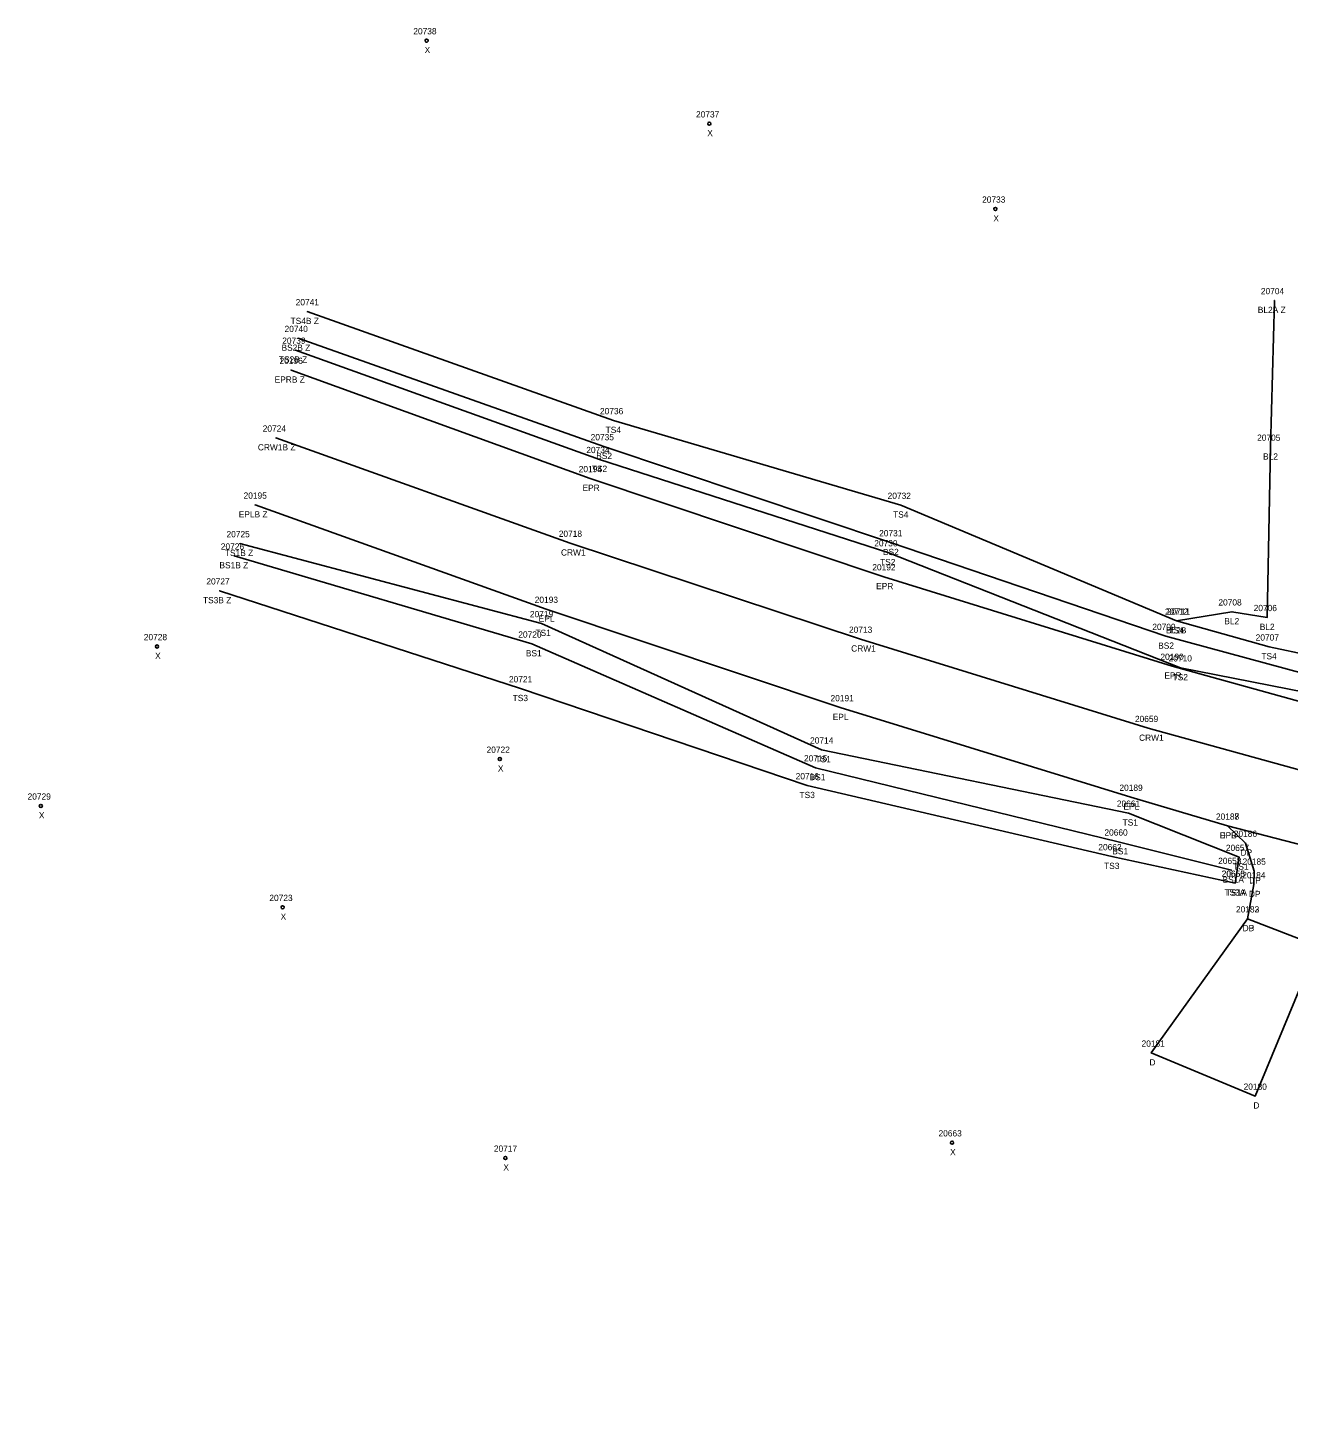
# Model space of a CAD drawing. Extents: x 1813127 to 1814107, y 1178171 to 1179078.
# Drawn here: x 1813127 to 1813328.5, y 1178708 to 1178931.8 of the extents above; entities that cross this region are included whole.
import ezdxf

# ---------------------------------------------------------------- set-up
doc = ezdxf.new("R2010")
doc.units = 0
for name, color, linetype in [('RD_DTM_BkLn1', 7, 'Continuous'), ('RD_DTM_BkLn2', 7, 'Continuous'), ('RD_EX_Driveway', 7, 'Continuous'), ('RD_EX_Driveway_txCode', 7, 'Continuous'), ('RD_EX_Road', 7, 'Continuous'), ('RD_EX_Road_txCode', 7, 'Continuous'), ('RD_SMD_Locator', 7, 'Continuous'), ('RD_SMD_Misc', 7, 'Continuous')]:
    doc.layers.add(name, color=color, linetype=linetype)

msp = doc.modelspace()

# ---------------------------------------------------------------- linework, layer by layer
at = {"layer": 'RD_DTM_BkLn1'}
for points in [[(1813326.2, 1178888.27), (1813325.6, 1178864.83), (1813325.07, 1178837.59), (1813319.4, 1178838.49), (1813310.54, 1178837.02)], [(1813740.76, 1178717.86), (1813693.97, 1178742.65), (1813652.18, 1178753.85), (1813643.74, 1178755.64), (1813595, 1178763.51), (1813546.44, 1178770.61), (1813497.6, 1178777.62), (1813448.59, 1178785.89), (1813401.09, 1178795.04), (1813353.48, 1178806.76), (1813306.05, 1178819.85), (1813260.03, 1178834.12), (1813213.64, 1178849.47), (1813166.61, 1178866.29)]]:
    msp.add_lwpolyline(points, dxfattribs=at)
at = {"layer": 'RD_DTM_BkLn2'}
for points in [[(1813399.11, 1178862.51), (1813400.66, 1178834.59), (1813396.83, 1178814.37), (1813357.41, 1178822.74), (1813331.9, 1178831.52), (1813325.37, 1178832.88), (1813310.54, 1178837.02), (1813266.49, 1178855.54), (1813220.54, 1178869.08), (1813171.6, 1178886.5)], [(1813400.27, 1178862.81), (1813401.78, 1178834.6), (1813398.4, 1178812.49), (1813398.37, 1178811.29), (1813357.2, 1178821.49), (1813308.85, 1178834.57), (1813264.85, 1178849.55), (1813219.03, 1178864.91), (1813170.13, 1178882.22)], [(1813401.59, 1178862.81), (1813403.02, 1178834.61), (1813400.13, 1178813.23), (1813399.37, 1178809.66), (1813357.07, 1178820.51), (1813311.17, 1178829.54), (1813264.4, 1178847.94), (1813218.33, 1178862.86), (1813169.73, 1178880.34)], [(1813319.93, 1178795.1), (1813320.59, 1178799.23), (1813302.9, 1178806.3), (1813253.81, 1178816.41), (1813209.04, 1178836.62), (1813160.82, 1178849.4)], [(1813319.35, 1178797.15), (1813301.23, 1178801.69), (1813252.84, 1178813.55), (1813207.5, 1178833.35), (1813159.94, 1178847.43)], [(1813319.93, 1178795.1), (1813300.22, 1178799.35), (1813251.54, 1178810.69), (1813205.69, 1178826.2), (1813157.6, 1178841.85)]]:
    msp.add_lwpolyline(points, dxfattribs=at)
at = {"layer": 'RD_EX_Driveway'}
for points in [[(1813343.23, 1178797.92), (1813338.76, 1178793.46), (1813333.1, 1178785.04), (1813321.9, 1178789.4), (1813322.9, 1178794.86), (1813322.95, 1178797.03), (1813321.57, 1178801.49), (1813318.7, 1178804.23)], [(1813333.1, 1178785.04), (1813323.15, 1178761.04), (1813306.52, 1178767.93), (1813321.9, 1178789.4)]]:
    msp.add_lwpolyline(points, dxfattribs=at)
at = {"layer": 'RD_EX_Road'}
for points in [[(1813499.47, 1178787.87), (1813450.56, 1178796.06), (1813414.35, 1178802.92), (1813398.64, 1178806.42), (1813355.44, 1178817.13), (1813309.85, 1178829.79), (1813263.76, 1178844.1), (1813216.84, 1178859.81), (1813169.03, 1178877.13)], [(1813732.94, 1178707.95), (1813689.88, 1178731.75), (1813641.71, 1178744.36), (1813593.37, 1178752.09), (1813544.49, 1178758.77), (1813495.45, 1178766.29), (1813446.8, 1178774.66), (1813426.54, 1178777.95), (1813403.21, 1178782.55), (1813398.65, 1178783.84), (1813350.68, 1178796.09), (1813343.23, 1178797.92), (1813318.7, 1178804.23), (1813303.26, 1178808.85), (1813256.8, 1178823.17), (1813209.81, 1178838.91), (1813163.27, 1178855.57)]]:
    msp.add_lwpolyline(points, dxfattribs=at)
at = {"layer": 'RD_SMD_Locator'}
for centre, radius in [((1813190.68, 1178929.83), 0.25), ((1813235.87, 1178916.54), 0.25), ((1813281.6, 1178902.91), 0.25), ((1813326.2, 1178888.27), 0.001), ((1813171.6, 1178886.5), 0.001), ((1813170.13, 1178882.22), 0.001), ((1813169.73, 1178880.34), 0.001), ((1813169.03, 1178877.13), 0.001), ((1813220.54, 1178869.08), 0.001), ((1813166.61, 1178866.29), 0.001), ((1813219.03, 1178864.91), 0.001), ((1813325.6, 1178864.83), 0.001), ((1813218.33, 1178862.86), 0.001), ((1813216.84, 1178859.81), 0.001), ((1813163.27, 1178855.57), 0.001), ((1813266.49, 1178855.54), 0.001), ((1813160.82, 1178849.4), 0.001), ((1813213.64, 1178849.47), 0.001), ((1813264.4, 1178847.94), 0.001), ((1813264.85, 1178849.55), 0.001), ((1813159.94, 1178847.43), 0.001), ((1813263.76, 1178844.1), 0.001), ((1813157.6, 1178841.85), 0.001), ((1813209.81, 1178838.91), 0.001), ((1813310.54, 1178837.02), 0.001), ((1813310.54, 1178837.02), 0.001), ((1813319.4, 1178838.49), 0.001), ((1813325.07, 1178837.59), 0.001), ((1813209.04, 1178836.62), 0.001), ((1813308.85, 1178834.57), 0.001), ((1813147.6, 1178832.94), 0.25), ((1813207.5, 1178833.35), 0.001), ((1813260.03, 1178834.12), 0.001), ((1813325.37, 1178832.88), 0.001), ((1813309.85, 1178829.79), 0.001), ((1813311.17, 1178829.54), 0.001), ((1813205.69, 1178826.2), 0.001), ((1813256.8, 1178823.17), 0.001), ((1813306.05, 1178819.85), 0.001), ((1813202.39, 1178814.93), 0.25), ((1813253.81, 1178816.41), 0.001), ((1813252.84, 1178813.55), 0.001), ((1813251.54, 1178810.69), 0.001), ((1813129.02, 1178807.44), 0.25), ((1813303.26, 1178808.85), 0.001), ((1813302.9, 1178806.3), 0.001), ((1813318.7, 1178804.23), 0.001), ((1813318.7, 1178804.23), 0.001), ((1813301.23, 1178801.69), 0.001), ((1813321.57, 1178801.49), 0.001), ((1813300.22, 1178799.35), 0.001), ((1813320.59, 1178799.23), 0.001), ((1813319.35, 1178797.15), 0.001), ((1813322.95, 1178797.03), 0.001), ((1813319.93, 1178795.1), 0.001), ((1813319.93, 1178795.1), 0.001), ((1813322.9, 1178794.86), 0.001), ((1813167.67, 1178791.23), 0.25), ((1813321.9, 1178789.4), 0.001), ((1813321.9, 1178789.4), 0.001), ((1813306.52, 1178767.93), 0.001), ((1813323.15, 1178761.04), 0.001), ((1813274.67, 1178753.58), 0.25), ((1813203.27, 1178751.13), 0.25)]:
    msp.add_circle(centre, radius, dxfattribs=at)

# ---------------------------------------------------------------- texts
at = {"layer": 'RD_EX_Driveway_txCode'}
for s, p in [('20187', (1813316.86, 1178805.23)), ('DPB', (1813317.44, 1178802.23)), ('20186', (1813319.71, 1178802.49)), ('DP', (1813320.79, 1178799.49)), ('20185', (1813321.11, 1178798.03)), ('20184', (1813321.06, 1178795.86)), ('DP', (1813322.17, 1178795.03)), ('DP', (1813322.12, 1178792.86)), ('20182', (1813320.06, 1178790.4)), ('20183', (1813320.06, 1178790.4)), ('DB', (1813321.12, 1178787.4)), ('DP', (1813321.12, 1178787.4)), ('20181', (1813304.97, 1178768.93)), ('D', (1813306.22, 1178765.93)), ('20180', (1813321.28, 1178762.04)), ('D', (1813322.84, 1178759.04))]:
    msp.add_text(s, height=1, dxfattribs=at).set_placement(p)
at = {"layer": 'RD_EX_Road_txCode'}
for s, p in [('20196', (1813167.17, 1178878.13)), ('EPRB Z', (1813166.39, 1178875.13)), ('20194', (1813215, 1178860.81)), ('20195', (1813161.43, 1178856.57)), ('EPR', (1813215.61, 1178857.81)), ('EPLB Z', (1813160.65, 1178853.57)), ('20192', (1813261.93, 1178845.1)), ('EPR', (1813262.54, 1178842.1)), ('20193', (1813207.97, 1178839.91)), ('EPL', (1813208.6, 1178836.91)), ('20190', (1813307.98, 1178830.79)), ('EPR', (1813308.62, 1178827.79)), ('20191', (1813255.25, 1178824.17)), ('EPL', (1813255.6, 1178821.17)), ('20189', (1813301.43, 1178809.85)), ('EPL', (1813302.06, 1178806.85)), ('20188', (1813316.86, 1178805.23)), ('EPL', (1813317.49, 1178802.23))]:
    msp.add_text(s, height=1, dxfattribs=at).set_placement(p)
at = {"layer": 'RD_SMD_Misc'}
for s, p in [('20738', (1813188.56, 1178930.83)), ('X', (1813190.37, 1178927.83)), ('20737', (1813233.75, 1178917.54)), ('X', (1813235.55, 1178914.54)), ('20733', (1813279.48, 1178903.91)), ('X', (1813281.28, 1178900.91)), ('20741', (1813169.76, 1178887.5)), ('20704', (1813324.04, 1178889.27)), ('BL2A Z', (1813323.55, 1178886.27)), ('20740', (1813167.98, 1178883.22)), ('TS4B Z', (1813168.94, 1178884.5)), ('20739', (1813167.61, 1178881.34)), ('TS2B Z', (1813167.07, 1178878.34)), ('BS2B Z', (1813167.49, 1178880.22)), ('20736', (1813218.4, 1178870.08)), ('20724', (1813164.49, 1178867.29)), ('TS4', (1813219.3, 1178867.08)), ('20735', (1813216.91, 1178865.91)), ('20705', (1813323.44, 1178865.83)), ('CRW1B Z', (1813163.71, 1178864.29)), ('20734', (1813216.21, 1178863.86)), ('BS2', (1813217.8, 1178862.91)), ('BL2', (1813324.39, 1178862.83)), ('TS2', (1813217.09, 1178860.86)), ('20732', (1813264.38, 1178856.54)), ('TS4', (1813265.25, 1178853.54)), ('20725', (1813158.7, 1178850.4)), ('20718', (1813211.81, 1178850.47)), ('20731', (1813263.02, 1178850.55)), ('20726', (1813157.79, 1178848.43)), ('TS1B Z', (1813158.44, 1178847.4)), ('CRW1', (1813212.16, 1178847.47)), ('20730', (1813262.24, 1178848.94)), ('BS2', (1813263.63, 1178847.55)), ('BS1B Z', (1813157.57, 1178845.43)), ('TS2', (1813263.16, 1178845.94)), ('20727', (1813155.48, 1178842.85)), ('TS3B Z', (1813154.94, 1178839.85)), ('20712', (1813308.71, 1178838.02)), ('20711', (1813308.99, 1178838.02)), ('20708', (1813317.25, 1178839.49)), ('20706', (1813322.89, 1178838.59)), ('20719', (1813207.2, 1178837.62)), ('BL2', (1813318.2, 1178836.49)), ('20728', (1813145.48, 1178833.94)), ('20720', (1813205.34, 1178834.35)), ('TS1', (1813208.08, 1178834.62)), ('20713', (1813258.2, 1178835.12)), ('20709', (1813306.69, 1178835.57)), ('BL2B', (1813308.86, 1178835.02)), ('TS4', (1813309.3, 1178835.02)), ('20707', (1813323.21, 1178833.88)), ('BL2', (1813323.86, 1178835.59)), ('BS1', (1813206.55, 1178831.35)), ('CRW1', (1813258.55, 1178832.12)), ('BS2', (1813307.62, 1178832.57)), ('X', (1813147.29, 1178830.94)), ('20710', (1813309.3, 1178830.54)), ('TS4', (1813324.12, 1178830.88)), ('20721', (1813203.85, 1178827.2)), ('TS2', (1813309.93, 1178827.54)), ('TS3', (1813204.44, 1178824.2)), ('20659', (1813303.91, 1178820.85)), ('CRW1', (1813304.57, 1178817.85)), ('20722', (1813200.27, 1178815.93)), ('20714', (1813251.98, 1178817.41)), ('20715', (1813251.01, 1178814.55)), ('TS1', (1813252.85, 1178814.41)), ('X', (1813202.08, 1178812.93)), ('20716', (1813249.68, 1178811.69)), ('BS1', (1813251.9, 1178811.55)), ('20729', (1813126.9, 1178808.44)), ('TS3', (1813250.29, 1178808.69)), ('20661', (1813301.02, 1178807.3)), ('X', (1813128.71, 1178805.44)), ('20660', (1813299.03, 1178802.69)), ('TS1', (1813301.94, 1178804.3)), ('20662', (1813298.06, 1178800.35)), ('20657', (1813318.45, 1178800.23)), ('BS1', (1813300.29, 1178799.69)), ('20658', (1813317.21, 1178798.15)), ('TS3', (1813298.98, 1178797.35)), ('20656', (1813317.76, 1178796.1)), ('20655', (1813317.79, 1178796.1)), ('TS1', (1813319.63, 1178797.23)), ('BS1A', (1813317.91, 1178795.15)), ('20723', (1813165.55, 1178792.23)), ('TS3A', (1813318.2, 1178793.1)), ('TS1A', (1813318.48, 1178793.1)), ('X', (1813167.35, 1178789.23)), ('20663', (1813272.51, 1178754.58)), ('20717', (1813201.44, 1178752.13)), ('X', (1813274.36, 1178751.58)), ('X', (1813202.96, 1178749.13))]:
    msp.add_text(s, height=1, dxfattribs=at).set_placement(p)

doc.saveas('drawing.dxf')
